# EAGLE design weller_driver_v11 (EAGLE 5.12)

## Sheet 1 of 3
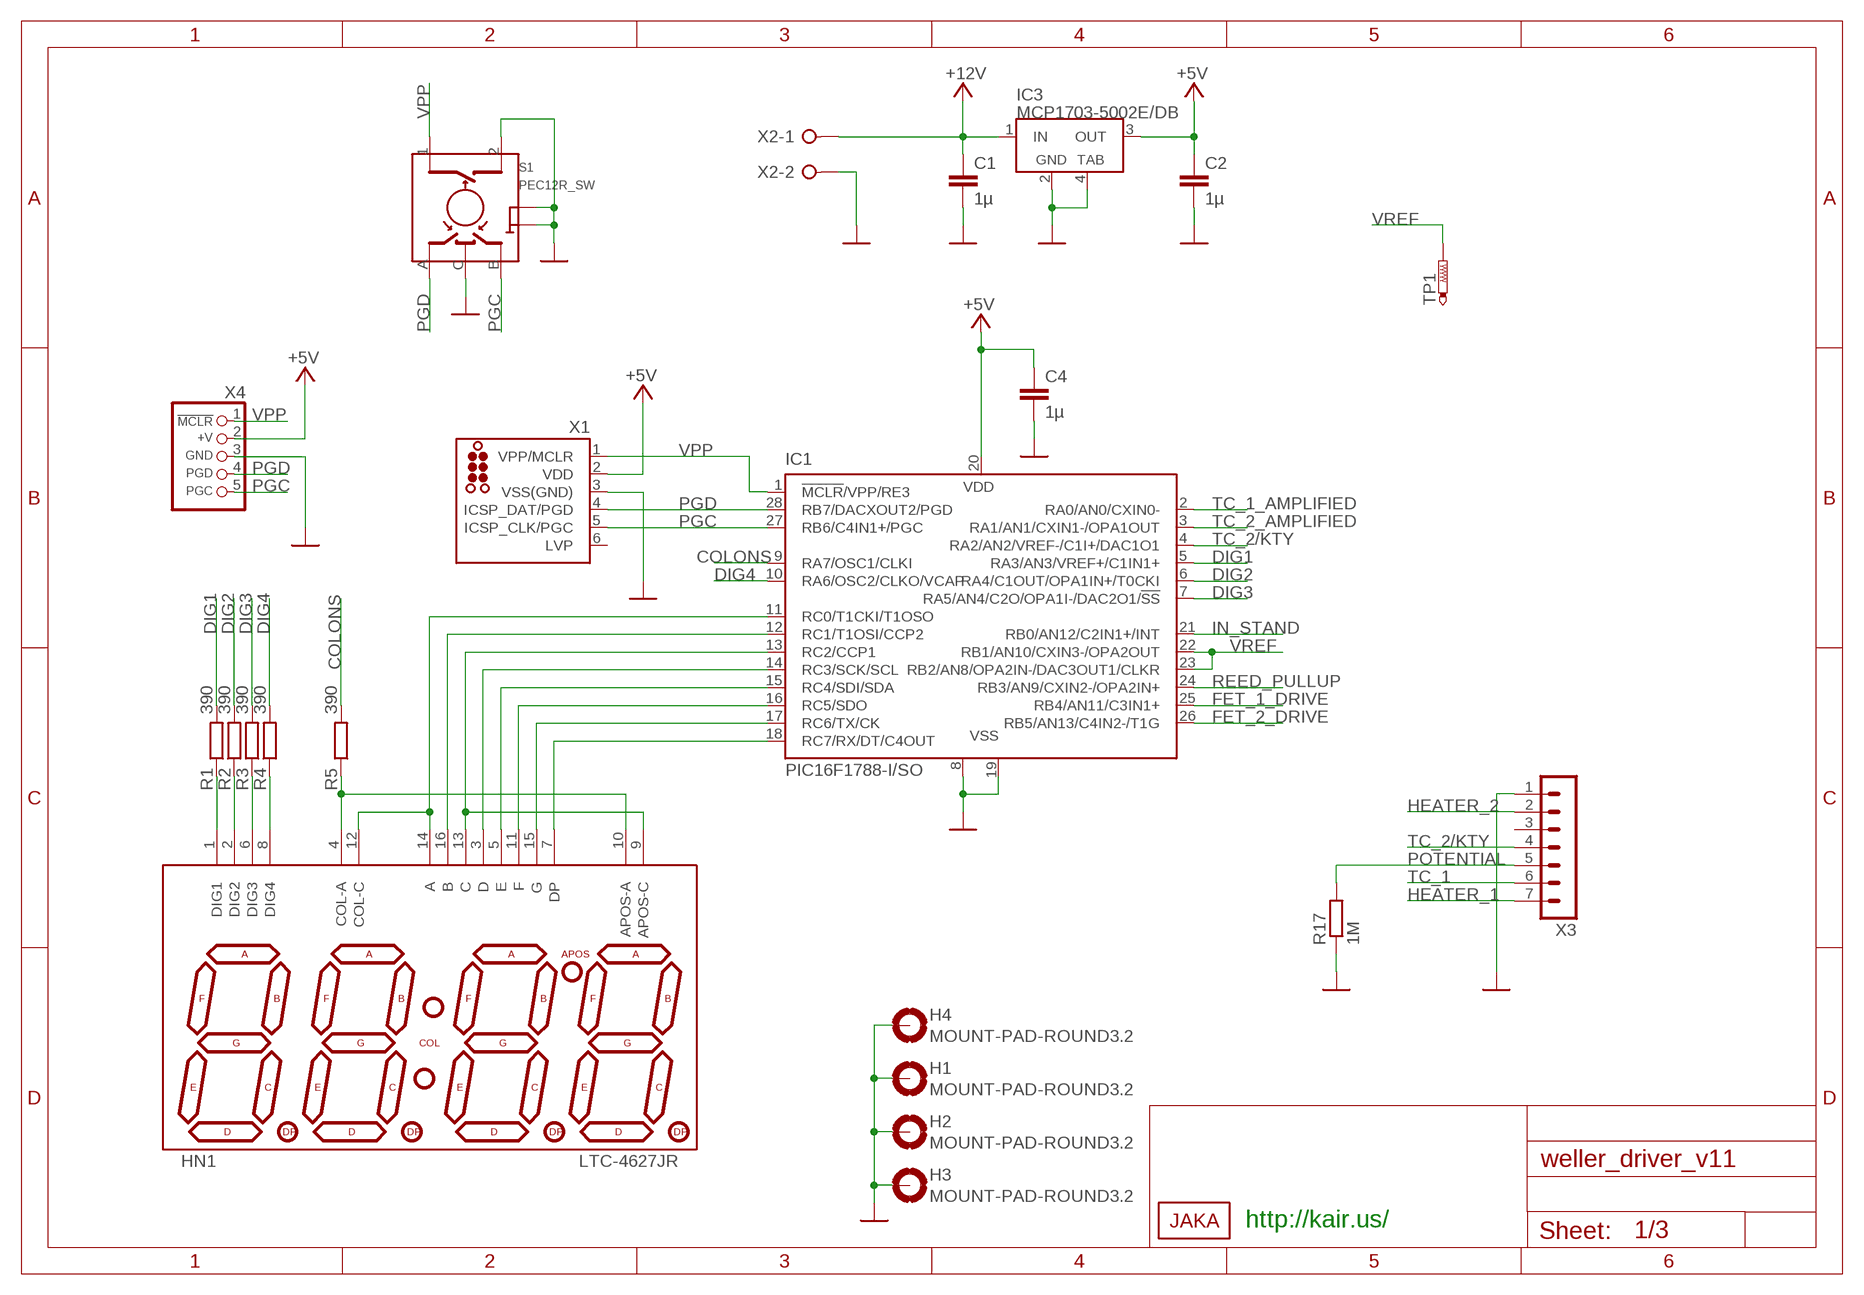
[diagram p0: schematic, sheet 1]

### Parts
C1  1µ  C-EUC0805  [C0805]
C2  1µ  C-EUC0805  [C0805]
C4  1µ  C-EUC0805  [C0805]
H1  MOUNT-PAD-ROUND3.2  [3,2-PAD]
H2  MOUNT-PAD-ROUND3.2  [3,2-PAD]
H3  MOUNT-PAD-ROUND3.2  [3,2-PAD]
H4  MOUNT-PAD-ROUND3.2  [3,2-PAD]
HN1  LTC-4627JR  7-SEGMENT-4DIGIT-YOUNGSUN  [7-SEGMENT-4DIGIT-YOUNGSUN]
IC1  PIC16F1788-I/SO  [SO28W]
IC3  MCP1703-5002E/DB  VREG_3PIN_FIXED_TAB-SOT223  [SOT223]
R1  390  R-EU_R0805  [R0805]
R2  390  R-EU_R0805  [R0805]
R3  390  R-EU_R0805  [R0805]
R4  390  R-EU_R0805  [R0805]
R5  390  R-EU_R0805  [R0805]
R17  1M  R-EU_R0805  [R0805]
S1  PEC12R_SW  [ALPS_EC12E_SW]
TP1  PTR1PAD1-13  [P1-13]
U$1  JAKA_LOGO_SILK_TINY  [JAKA_SILK_TINY]
X1  TC2030-MCP-NL-JKA  [TC2030-MCP-NL-JKA]
X2  W237-02P  [W237-132]
X3  MA07-1  [MA07-1]
X4  CON_HEADER_PRG_PIC_ICSPB  [HEADER_PRG_1X05_ICSP_B]

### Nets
+5V [supply]: C2.1 C4.1 IC1.20(VDD) IC3.3(OUT) X1.2(VDD) X4.2(+V) ; also sheet 2
+12V [iron_power]: C1.1 IC3.1(IN) X2.1 ; also sheet 2
COLONS: IC1.9(RA7/OSC1/CLKI) R5.2
DIG1: IC1.5(RA3/AN3/VREF+/C1IN1+) R1.2
DIG2: IC1.6(RA4/C1OUT/OPA1IN+/T0CKI) R2.2
DIG3: IC1.7(RA5/AN4/C2O/OPA1I-/DAC2O1/!SS) R3.2
DIG4: IC1.10(RA6/OSC2/CLKO/VCAP) R4.2
FET_1_DRIVE: IC1.25(RB4/AN11/C3IN1+) ; also sheet 2
FET_2_DRIVE: IC1.26(RB5/AN13/C4IN2-/T1G) ; also sheet 2
GND [supply]: C1.2 C2.2 C4.2 H1.B3,2(MOUNT) H2.B3,2(MOUNT) H3.B3,2(MOUNT) H4.B3,2(MOUNT) IC1.8(VSS) IC1.19(VSS) IC3.2(GND) IC3.4(GND1) R17.1 S1.2 S1.C S1.GND1(GND) S1.GND2(GND) X1.3(VSS(GND)) X2.2 X3.1 X4.3(GND) ; also sheet 2
HEATER_1 [iron_power]: X3.7 ; also sheet 2
HEATER_2 [iron_power]: X3.2 ; also sheet 2
IN_STAND: IC1.21(RB0/AN12/C2IN1+/INT) ; also sheet 2
N$1: HN1.1(DIG1) R1.1
N$2: HN1.2(DIG2) R2.1
N$3: HN1.6(DIG3) R3.1
N$4: HN1.8(DIG4) R4.1
N$5: HN1.4(COL-A) HN1.10(APOS-A) R5.1
N$6: HN1.12(COL-C) HN1.14(A) IC1.11(RC0/T1CKI/T1OSO)
N$7: HN1.9(APOS-C) HN1.13(C) IC1.13(RC2/CCP1)
N$13: HN1.16(B) IC1.12(RC1/T1OSI/CCP2)
N$17: HN1.3(D) IC1.14(RC3/SCK/SCL)
N$18: HN1.5(E) IC1.15(RC4/SDI/SDA)
N$19: HN1.11(F) IC1.16(RC5/SDO)
N$20: HN1.7(DP) IC1.18(RC7/RX/DT/C4OUT)
N$21: HN1.15(G) IC1.17(RC6/TX/CK)
PGC: IC1.27(RB6/C4IN1+/PGC) S1.B X1.5(ICSP_CLK/PGC) X4.5(PGC)
PGD: IC1.28(RB7/DACXOUT2/PGD) S1.A X1.4(ICSP_DAT/PGD) X4.4(PGD)
POTENTIAL: R17.2 X3.5
REED_PULLUP: IC1.24(RB3/AN9/CXIN2-/OPA2IN+) ; also sheet 2
TC_1: X3.6 ; also sheet 2
TC_1_AMPLIFIED: IC1.2(RA0/AN0/CXIN0-) ; also sheet 2
TC_2/KTY: IC1.4(RA2/AN2/VREF-/C1I+/DAC1O1) X3.4 ; also sheet 2
TC_2_AMPLIFIED: IC1.3(RA1/AN1/CXIN1-/OPA1OUT) ; also sheet 2
VPP: IC1.1(!MCLR!/VPP/RE3) S1.1 X1.1(VPP/MCLR) X4.1(/MCLR)
VREF: IC1.22(RB1/AN10/CXIN3-/OPA2OUT) IC1.23(RB2/AN8/OPA2IN-/DAC3OUT1/CLKR) TP1.TP ; also sheet 2
Unconnected: X1.6(LVP) X3.3

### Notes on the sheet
- http://kair.us/

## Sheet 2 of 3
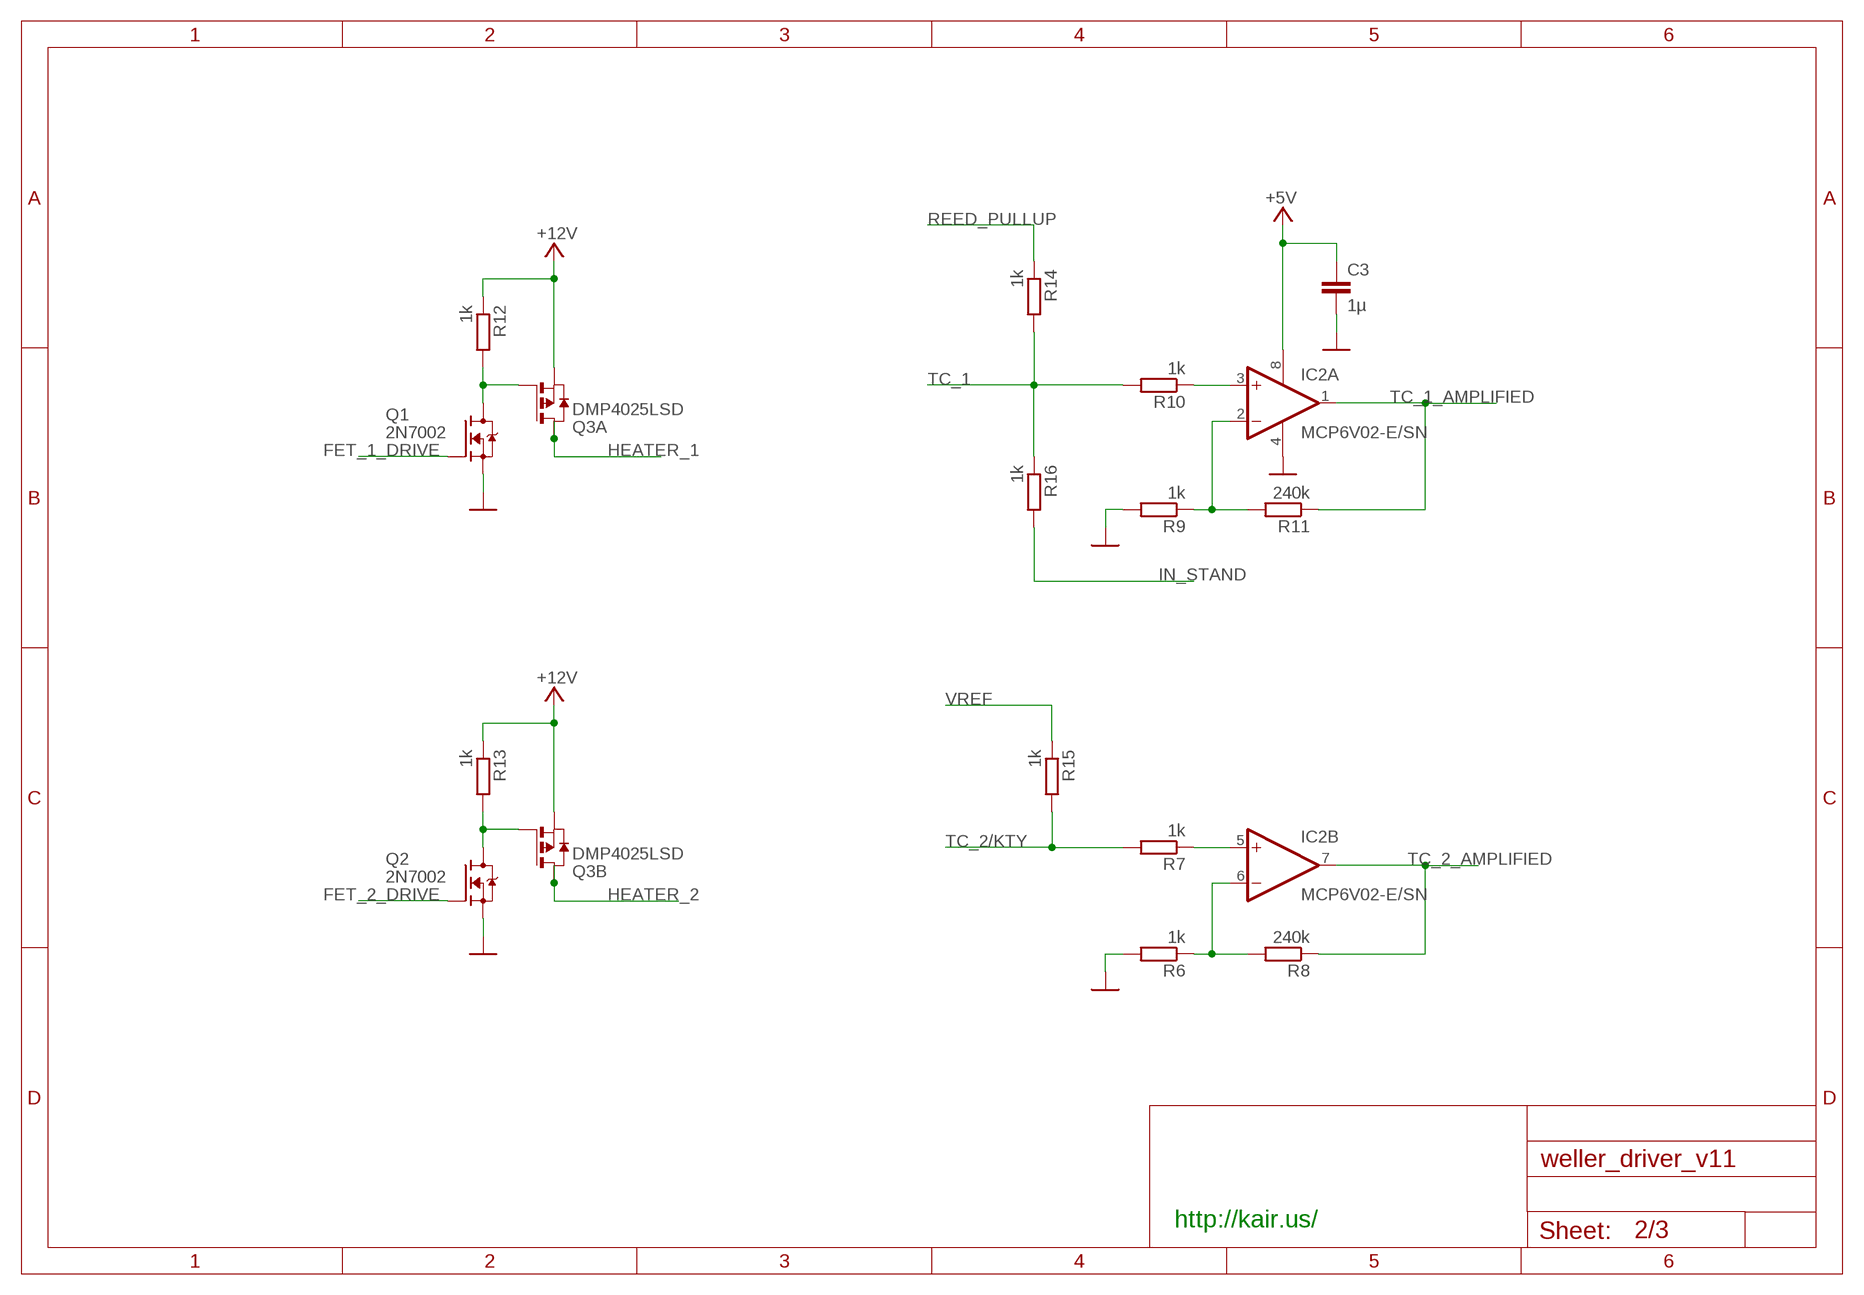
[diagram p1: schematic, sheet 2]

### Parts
C3  1µ  C-EUC0805  [C0805]
IC2  MCP6V02-E/SN  MCP602SN  [SO08]
Q1  2N7002  TRANSISTOR_FET_BS170-SOT-23  [SOT-23]
Q2  2N7002  TRANSISTOR_FET_BS170-SOT-23  [SOT-23]
Q3  DMP4025LSD  PMOS2SO8  [SO08]
R6  1k  R-EU_R0805  [R0805]
R7  1k  R-EU_R0805  [R0805]
R8  240k  R-EU_R0805  [R0805]
R9  1k  R-EU_R0805  [R0805]
R10  1k  R-EU_R0805  [R0805]
R11  240k  R-EU_R0805  [R0805]
R12  1k  R-EU_R0805  [R0805]
R13  1k  R-EU_R0805  [R0805]
R14  1k  R-EU_R0805  [R0805]
R15  1k  R-EU_R0805  [R0805]
R16  1k  R-EU_R0805  [R0805]

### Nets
+5V [supply]: C3.1 IC2.8(P:V+) ; also sheet 1
+12V [iron_power]: Q3.1(A:S) Q3.3(B:S) R12.1 R13.1 ; also sheet 1
FET_1_DRIVE: Q1.1(G) ; also sheet 1
FET_2_DRIVE: Q2.1(G) ; also sheet 1
GND [supply]: C3.2 IC2.4(P:V-) Q1.2(S) Q2.2(S) R6.2 R9.2 ; also sheet 1
HEATER_1 [iron_power]: Q3.7(A:D) Q3.8(A:D2) ; also sheet 1
HEATER_2 [iron_power]: Q3.5(B:D2) Q3.6(B:D) ; also sheet 1
IN_STAND: R16.2 ; also sheet 1
N$22: IC2.3(A:+IN) R10.1
N$23: IC2.2(A:-IN) R9.1 R11.2
N$25: IC2.6(B:-IN) R6.1 R8.2
N$27: IC2.5(B:+IN) R7.1
N$28: Q1.3(D) Q3.2(A:G) R12.2
N$42: Q2.3(D) Q3.4(B:G) R13.2
REED_PULLUP: R14.1 ; also sheet 1
TC_1: R10.2 R14.2 R16.1 ; also sheet 1
TC_1_AMPLIFIED: IC2.1(A:OUT) R11.1 ; also sheet 1
TC_2/KTY: R7.2 R15.2 ; also sheet 1
TC_2_AMPLIFIED: IC2.7(B:OUT) R8.1 ; also sheet 1
VREF: R15.1 ; also sheet 1

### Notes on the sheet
- http://kair.us/

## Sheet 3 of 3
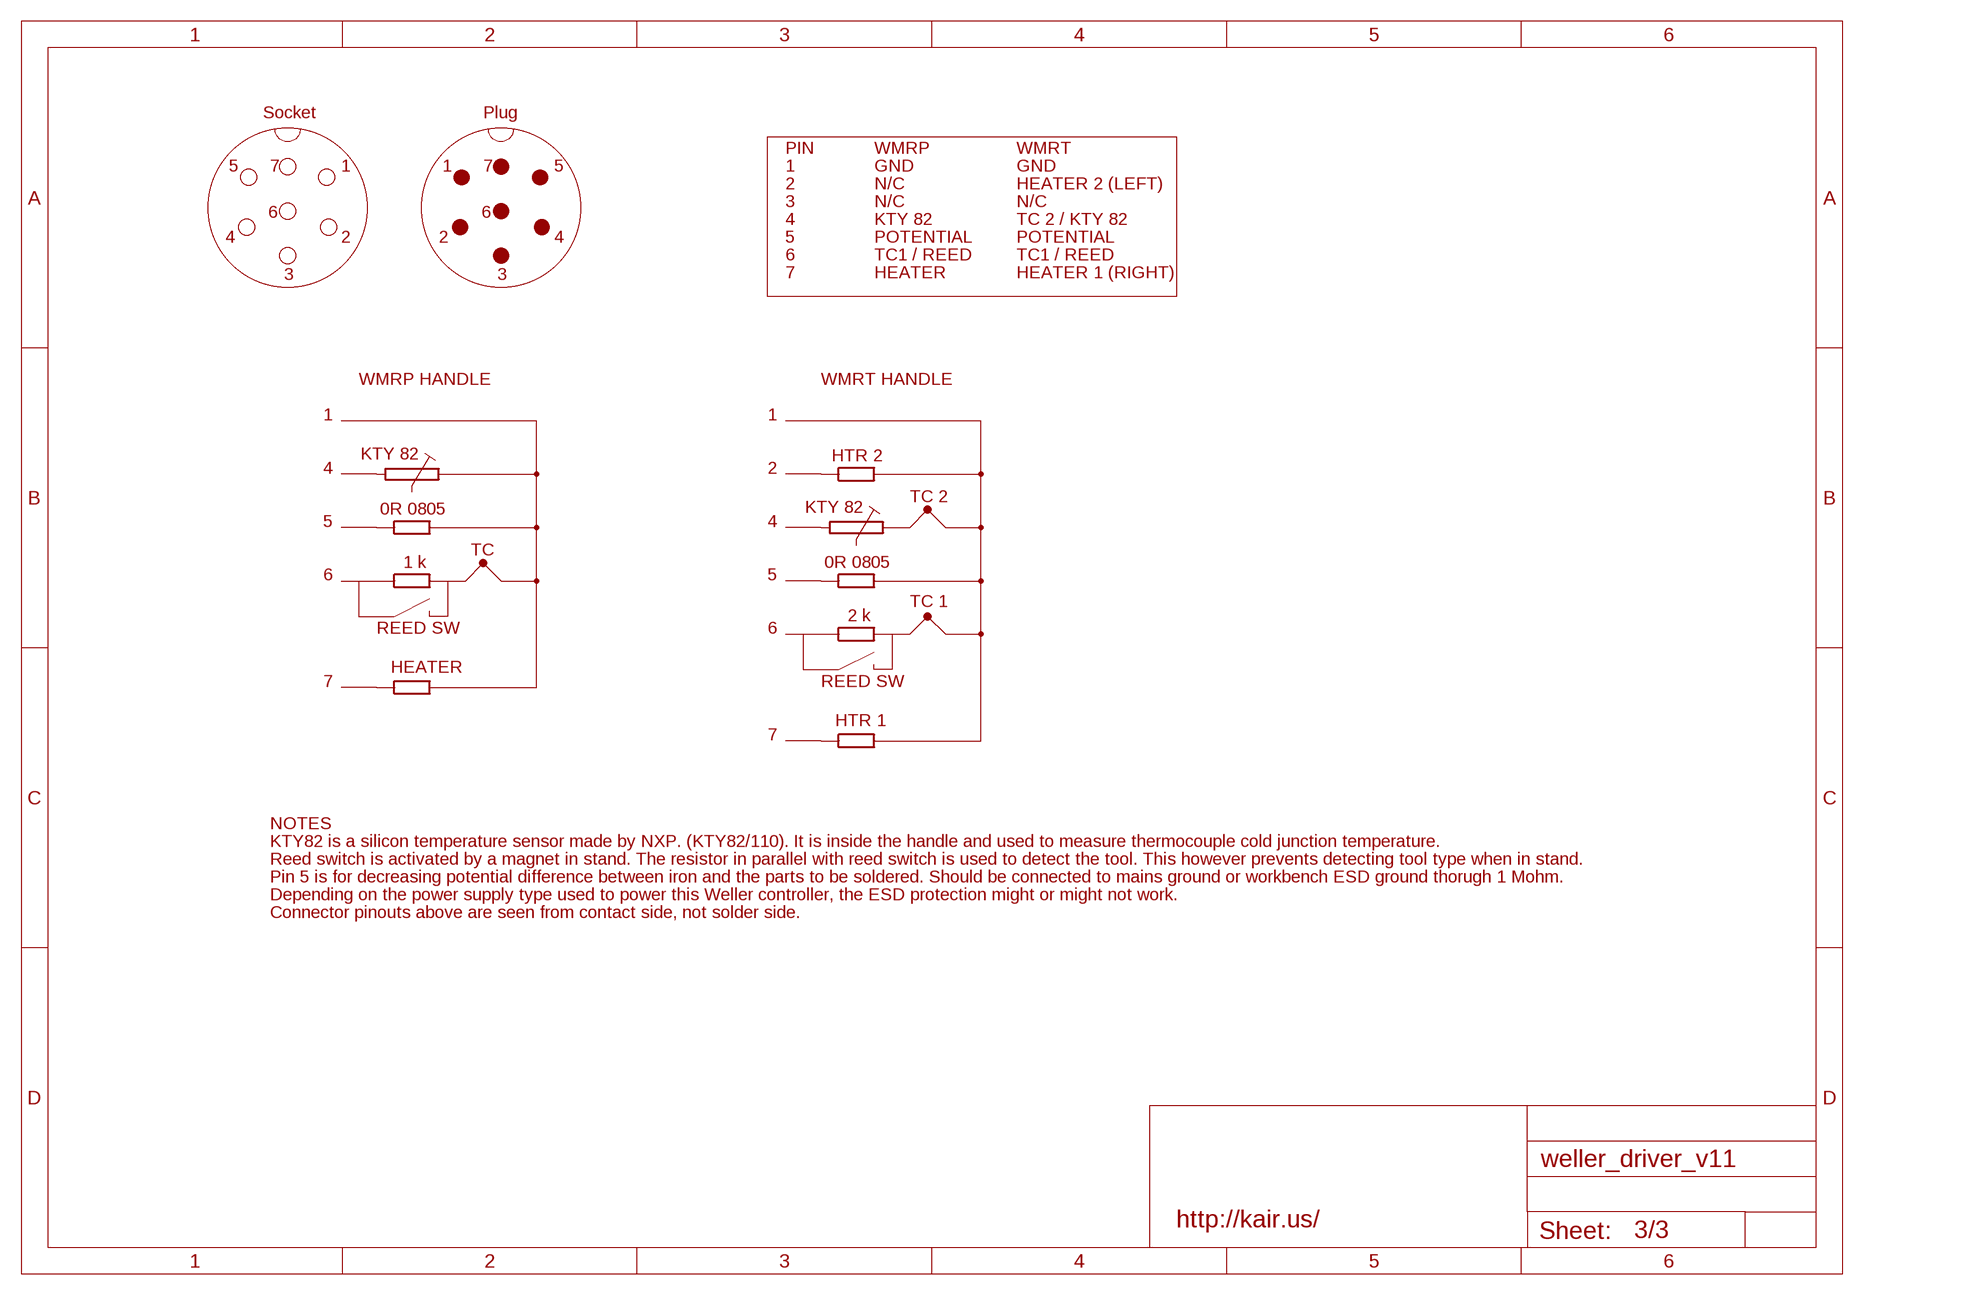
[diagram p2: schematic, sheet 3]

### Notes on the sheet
- Socket | Plug
- PIN | WMRP | WMRT
- 5 | 7 | 1 | 1 | 7 | 5 | 1 | GND | GND
- 2 | N/C | HEATER 2 (LEFT)
- 3 | N/C | N/C
- 6 | 6
- 4 | KTY 82 | TC 2 / KTY 82
- 4 | 2 | 2 | 4 | 5 | POTENTIAL | POTENTIAL
- 6 | TC1 / REED | TC1 / REED
- 3 | 3 | 7 | HEATER | HEATER 1 (RIGHT)
- WMRP HANDLE | WMRT HANDLE
- 1 | 1
- KTY 82 | HTR 2
- 4 | 2
- TC 2
- 0R 0805 | KTY 82
- 5 | 4
- TC
- 1 k | 0R 0805
- 6 | 5
- TC 1
- 2 k
- REED SW | 6
- HEATER
- 7 | REED SW
- HTR 1
- 7
- NOTES
- KTY82 is a silicon temperature sensor made by NXP. (KTY82/110). It is inside the handle and used to measure thermocouple cold junction temperature.
- Reed switch is activated by a magnet in stand. The resistor in parallel with reed switch is used to detect the tool. This however prevents detecting tool type when in stand.
- Pin 5 is for decreasing potential difference between iron and the parts to be soldered. Should be connected to mains ground or workbench ESD ground thorugh 1 Mohm.
- Depending on the power supply type used to power this Weller controller, the ESD protection might or might not work.
- Connector pinouts above are seen from contact side, not solder side.
- http://kair.us/

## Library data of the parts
C1-C4 = dual_atari:C-EU: CAPACITOR, European symbol
H1-H4 = dual_atari:MOUNT-PAD-ROUND: MOUNTING PAD, round
HN1 = omat:7-SEGMENT-4DIGIT-YOUNGSUN: This is a part for the 4-Digit 7-segment LEDs from Young Sun. Different from the Digikey LEDs, all 16 pins are used. The LONGPADS Variant is used for a test jig, but you may like it because there is more pad to solder to. If you are concerned about routing space, the standard works just fine though.
IC1 = omat:PIC16F1788
IC2 = omat:MCP602: Single Op Amp 2.7V to 6.0V Single Supply CMOS Source: http://ww1.microchip.com/downloads/en/DeviceDoc/21314g.pdf
IC3 = omat:VREG_3PIN_FIXED_TAB
Q1 Q2 = omat:TRANSISTOR_FET_BS170: N-Channel Enhancement Mode Field Effect Transistor
Q3 = omat:PMOS2: DUAL 30V P-CHANNEL ENHANCEMENT MODE MOSFET Source: Data sheet SOP8 Source: Data sheet MSOP8
R1-R17 = dual_atari:R-EU_: RESISTOR, European symbol
S1 = omat:PEC12R_SW
TP1 = testpad:PTR1: TEST PIN
U$1 = dual_atari:JAKA_LOGO
X1 = dual_atari:TC2030: TAG-CONNECT ISP Connector Manufacturer: Tag-Connect Cable for easy In-Circuit PCB Programming. Designed for Microchip ICD2, suitable for many others. Two variants - one "with legs" (for hads-free fit on PCB) and another "without legs" for quick programming. PADDescription 1MCLR/Vpp 2Vdd 3GND 4PGD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
X2 = omat:W237-02P: WAGO SREW CLAMP; OC_FARNELL: unknown; OC_NEWARK: unknown
X3 = omat:MA07-1: PIN HEADER; OC_FARNELL: unknown; OC_NEWARK: unknown
X4 = omat:CON_HEADER_PRG_PIC_ICSP: 5-pin PIC In Circuit Serial Programming header

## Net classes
1 supply: width 0.4 mm, drill 0.7 mm, clearance 0.25 mm
2 iron_power: width 1 mm, drill 0.7 mm, clearance 0.25 mm

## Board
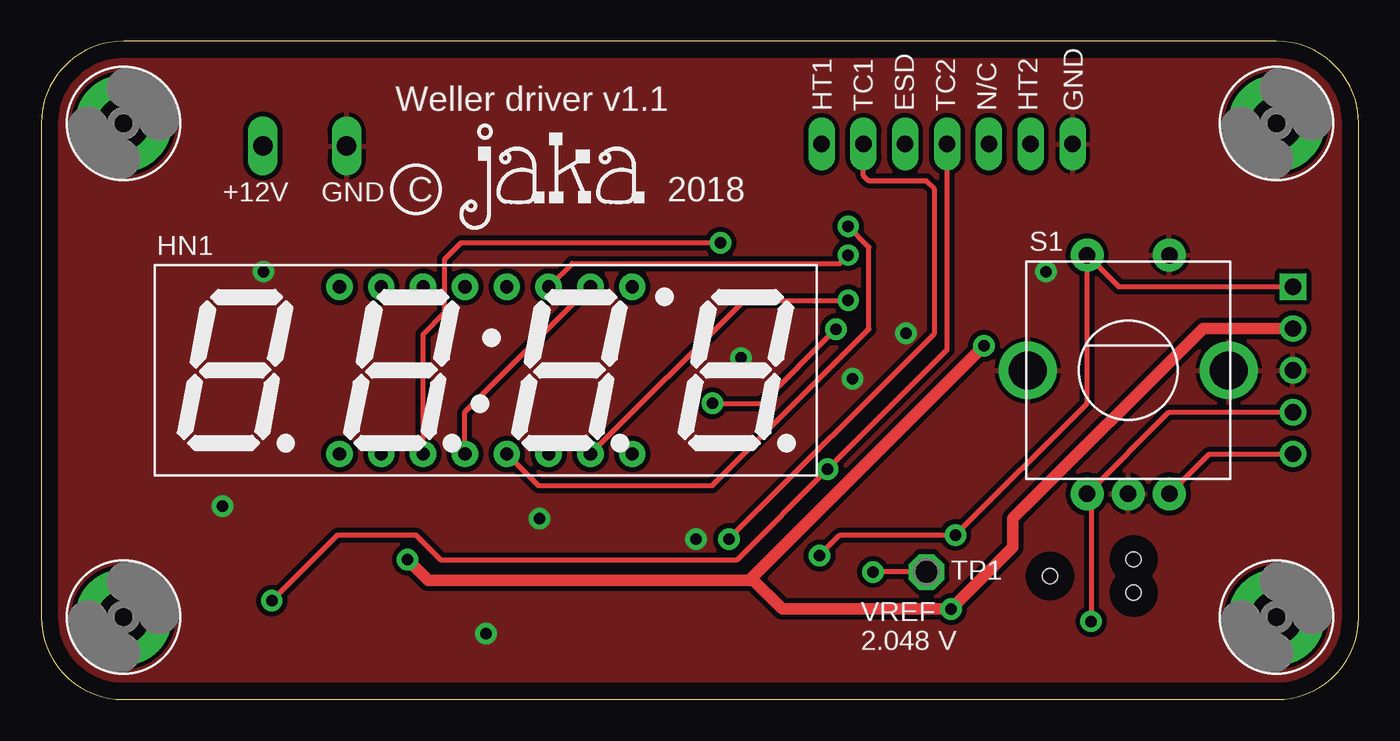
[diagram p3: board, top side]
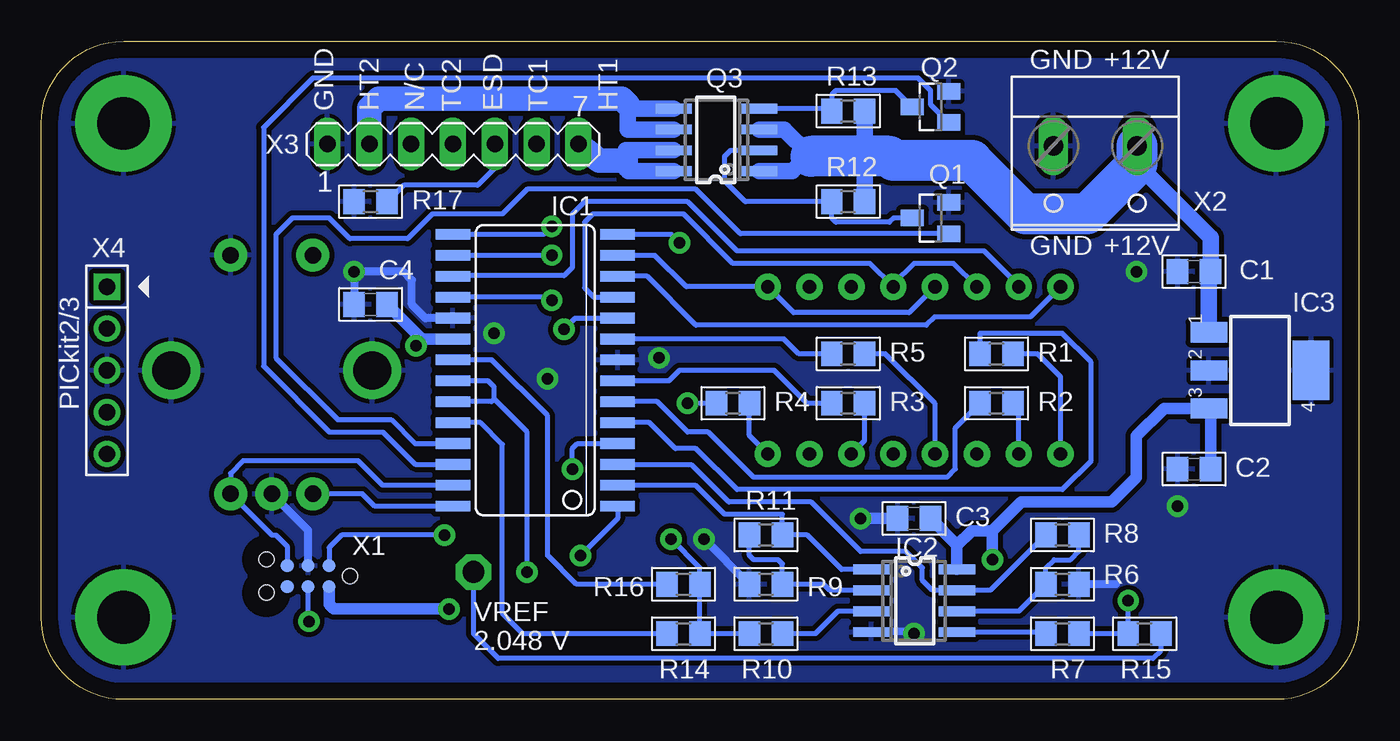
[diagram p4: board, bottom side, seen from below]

Size 80 x 40 mm. Coordinates in mm from the lower left corner, seen from the top.
Outline: 75,0 arc90 80,5 80,35 arc90 75,40 5,40 arc90 0,35 0,5 arc90 5,0 75,0
Copper layers (1*16): Top 0.035mm / dielectric 1.5mm / Bottom 0.035mm
Design rules "default *": minimum track width 0.25mm, minimum drill 0.7mm, track to track 0.25mm, track to pad 0.25mm, pad to pad 0.25mm, via to via 0.25mm, smd to smd 0.25mm, copper to edge 40mil, drill to drill 8mil, minimum pad ring 0.3mm, minimum via ring 0.3mm, stop-mask expansion 4mil, vias tented up to drill 0mil, thermal gap 10mil

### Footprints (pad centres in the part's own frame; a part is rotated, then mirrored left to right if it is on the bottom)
C0805 = smd 1.3 x 1.5: 1 -1,0; 2 1,0
3,2-PAD = drill 3.2 pad 5.842 round: B3,2 0,0
7-SEGMENT-4DIGIT-YOUNGSUN = drill 0.8 pad 1.6 round: 1 -8.89,-5.08; 2 -6.35,-5.08; 3 -3.81,-5.08; 4 -1.27,-5.08; 5 1.27,-5.08; 6 3.81,-5.08; 7 6.35,-5.08; 8 8.89,-5.08; 9 8.89,5.08; 10 6.35,5.08; 11 3.81,5.08; 12 1.27,5.08; 13 -1.27,5.08; 14 -3.81,5.08; 15 -6.35,5.08; 16 -8.89,5.08
SO28W = smd 0.65 x 2.1: 1 -8.255,-5; 2 -6.985,-5; 3 -5.715,-5; 4 -4.445,-5; 5 -3.175,-5; 6 -1.905,-5; 7 -0.635,-5; 8 0.635,-5; 9 1.905,-5; 10 3.175,-5; 11 4.445,-5; 12 5.715,-5; 13 6.985,-5; 14 8.255,-5; 15 8.255,5; 16 6.985,5; 17 5.715,5; 18 4.445,5; 19 3.175,5; 20 1.905,5; 21 0.635,5; 22 -0.635,5; 23 -1.905,5; 24 -3.175,5; 25 -4.445,5; 26 -5.715,5; 27 -6.985,5; 28 -8.255,5
SO08 = smd 0.6 x 2.2: 1 -1.905,-2.6; 2 -0.635,-2.6; 3 0.635,-2.6; 4 1.905,-2.6; 5 1.905,2.6; 6 0.635,2.6; 7 -0.635,2.6; 8 -1.905,2.6
SOT223 = smd 1.219 x 2.235: 1 -2.311,-3.099; 2 0,-3.099; 3 2.311,-3.099 | smd 3.6 x 2.2: 4 0,3.099
SOT-23 = smd 1 x 1.4: 1 -0.95,-1.1; 2 0.95,-1.1; 3 0,1.1
R0805 = smd 1.3 x 1.5: 1 -1,0; 2 1,0
ALPS_EC12E_SW = drill 1 pad 2 round: 1 -2.5,7; 2 2.5,7; A -2.5,-7.5; B 2.5,-7.5; C 0,-7.5 | drill 2.3 pad 3.5 round: GND1 -6.1,0; GND2 6.1,0
P1-13 = drill 1.321 pad 2.159 octagon: TP 0,0
TC2030-MCP-NL-JKA = smd 0.787 x 0.787: 1 1.27,-0.635; 2 1.27,0.635; 3 2.54,-0.635; 4 2.54,0.635; 5 3.81,-0.635; 6 3.81,0.635 | hole 0.9: 0,0; 5.08,-1.016; 5.08,1.016
W237-132 = drill 1.194 long: 1 -2.54,-0.635; 2 2.54,-0.635
MA07-1 = drill 1 long: 1 -7.62,0; 2 -5.08,0; 3 -2.54,0; 4 0,0; 5 2.54,0; 6 5.08,0; 7 7.62,0
HEADER_PRG_1X05_ICSP_B = drill 1 square: 1 -5.08,0 | drill 1 round: 2 -2.54,0; 3 0,0; 4 2.54,0; 5 5.08,0

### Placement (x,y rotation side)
C1  10,26 180 bottom
C2  10,14 180 bottom
C3  27,11 180 bottom
C4  60,24 180 bottom
H1  5,5 0 top
H2  75,5 0 top
H3  5,35 0 top
H4  75,35 0 top
HN1  27,20 0 top
IC1  50,20 90 bottom
IC2  27,6 270 bottom
IC3  6,20 270 bottom
Q1  26,29.25 90 bottom
Q2  26,36 90 bottom
Q3  39,34 90 bottom
R1  22,21 180 bottom
R2  22,18 180 bottom
R3  31,18 180 bottom
R4  38,18 180 bottom
R5  31,21 180 bottom
R6  18,7 0 bottom
R7  18,4 0 bottom
R8  18,10 0 bottom
R9  36,7 180 bottom
R10  36,4 180 bottom
R11  36,10 180 bottom
R12  31,30.25 180 bottom
R13  31,35.75 180 bottom
R14  41,4 0 bottom
R15  13,4 180 bottom
R16  41,7 180 bottom
R17  60,30.25 0 bottom
S1  66,20 0 top
TP1  53.75,7.75 0 top
U$1  31,31.75 0 top
X1  61.25,7.5 180 bottom
X2  16,33 180 bottom
X3  55,33.75 0 bottom
X4  76,20 270 bottom

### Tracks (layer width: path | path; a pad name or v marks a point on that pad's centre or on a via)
+5V  (via drill 0.7)
  Top 0.7: 43.12,7.38 43,7.25 23.5,7.25 v22.25,8.5 | 43.12,7.38 v57.25,21.5 | 43.12,7.38 45,5.5 v55.25,5.5 59,9.25 59,11 70.54,22.54 X4.2
  Bottom 0.5: 9,17.59 IC3.3
  Bottom 0.7: C2.1 9,17.59 | C3.1 24.4,9.4 IC2.8 24.4,9.35 23.5,10.25 22.25,10.25 | IC3.3 11.81,17.69 13.5,16 13.5,13.5 15,12 20.5,12 22.25,10.25 | 56.91,21.91 IC1.20 | 56.91,21.91 C4.1 | 56.91,21.91 56.91,21.84 v57.25,21.5 | X1.2 62.52,5.77 62.25,5.5 v55.25,5.5 | 22.25,10.25 v22.25,8.5
+12V
  Bottom 1: 13.46,32.54 9,28.08 C1.1 9.1,25.9 IC3.1 | R13.1 30,33 R12.1 | Q3.3 34.88,34.63 33.38,33.12 | 33.25,33 33.38,33.12 | Q3.1 34.41,32.09 33.38,33.12
  Bottom 2: 28.25,32.75 28.5,33
  Bottom 2.5: X2.1 13.46,32.54 16.5,29.5 20.25,29.5 23.5,32.75 28.25,32.75 | 28.5,33 30,33 33.25,33
COLONS
  Bottom 0.3: R5.2 34,21 34.91,21.91 IC1.9
DIG1
  Bottom 0.3: IC1.5 43.08,16.82 41.5,15.25 40.25,15.25 37.75,12.75 18,12.75 16.25,14.5 16.25,20.5 18,22.25 23,22.25 R1.2
DIG2
  Bottom 0.3: R2.2 24.5,16.5 24.5,14 25,13.5 36.75,13.5 39.5,16.25 40.75,16.25 42.59,18.09 IC1.6
DIG3
  Bottom 0.3: R3.2 33.5,18 35.5,20 41.25,20 41.88,19.36 IC1.7
DIG4  (via drill 0.7)
  Top 0.3: v40.75,18 43.75,18 v48.25,22.5
  Bottom 0.3: R4.2 v40.75,18 | v48.25,22.5 47.58,23.18 IC1.10
FET_1_DRIVE
  Bottom 0.3: IC1.25 57.3,15.55 58.75,17 62,17 65.75,20.75 65.75,28.25 64.75,29.25 62.5,29.25 61.25,28 57.75,28 56.25,29.5 52,29.5 50.5,31 40.25,31 37.55,28.3 Q1.1
FET_2_DRIVE
  Bottom 0.3: IC1.26 57.28,14.29 59.25,16.25 62.5,16.25 66.5,20.25 66.5,34.75 63.5,37.75 26.75,37.75 26,37 26,36.15 Q2.1
GND  (via drill 0.7)
  Bottom 0.5: IC2.4 27.1,4.15 v27,4 | R9.2 v39.75,9.75 | 14.75,7 R6.2 | IC1.19 56.67,23.18 57.5,24 57.5,25.5 58,26 60.5,26 61,25.5 C4.2 | S1.C 63.79,10.29 X1.3
  Bottom 0.7: C3.2 v30.25,11
  other vias: 13.5,26 11,11.75 42.5,20.75 52.5,22.25 49.25,19.5 61,26
  pour Top (isolate 0.3): 5,0 75,0 arc90 80,5 80,35 arc90 75,40 5,40 arc90 0,35 0,5 arc90
  pour Bottom (isolate 0.3): 5,0 75,0 arc90 80,5 80,35 arc90 75,40 5,40 arc90 0,35 0,5 arc90
HEATER_1
  Bottom 1: Q3.7 44.5,33.37 44.5,32.75 44.5,32.25 44.34,32.09 Q3.8
  Bottom 1.5: X3.7 46.13,32.75 44.5,32.75
HEATER_2
  Bottom 1: Q3.6 44.38,34.63 44.38,35.75 | 44.38,35.75 44.38,36.13 | Q3.5 44.23,35.91 44.38,35.75
  Bottom 1.5: X3.2 60.08,35.92 59.5,36.5 44.75,36.5 44.38,36.13
IN_STAND
  Bottom 0.3: R16.2 47.5,7 49.25,8.75 49.25,17.25 52.63,20.64 IC1.21
N$1
  Bottom 0.3: R1.1 19.5,21 18.11,19.61 HN1.1
N$2
  Bottom 0.3: HN1.2 20.65,17.65
  Bottom 0.5: 20.65,17.65 R2.1
N$3
  Bottom 0.3: HN1.6 30,15.73 R3.1
N$4
  Bottom 0.3: HN1.8 37,16.03 R4.1
N$5
  Top 0.3: HN1.10 25.73,17.46 HN1.4
  Bottom 0.3: R5.1 28.75,21 25.73,17.98 HN1.4
N$6
  Bottom 0.3: IC1.11 46.45,24.45 47,25 47,29 46.5,29.5 41,29.5 38,26.5 29.69,26.5 HN1.12 | 28.27,25.23 27,26.5 24.61,26.5 HN1.14
  Bottom 0.5: 28.27,25.23 HN1.12
N$7
  Bottom 0.3: HN1.13 27.31,23.5 34.31,23.5 HN1.9 40.83,25.08 42.73,26.98 IC1.13
N$13
  Bottom 0.3: IC1.12 43.22,25.71 40.25,22.75 26.25,22.75 25.75,23.25 19.94,23.25 HN1.16
N$17  (via drill 0.7)
  Top 0.3: v41.25,27.75 25.5,27.75 24.5,26.75 24.5,23.5 23.19,22.19 HN1.3
  Bottom 0.3: IC1.14 41.74,28.25 v41.25,27.75
N$18  (via drill 0.7)
  Top 0.3: HN1.5 30.19,13 40.75,13 50.25,22.5 50.25,27.5 v49,28.75
  Bottom 0.3: IC1.15 49.49,28.25 v49,28.75
N$19  (via drill 0.7)
  Top 0.3: v49,27 48.5,26.5 32.23,26.5 HN1.11
  Bottom 0.3: IC1.16 49.52,26.98 v49,27
N$20  (via drill 0.7)
  Top 0.3: v49,24.25 42.68,24.25 HN1.7
  Bottom 0.3: IC1.18 49.2,24.45 v49,24.25
N$21
  Bottom 0.3: 20.65,25.15 22.75,27.25 37.75,27.25 40.75,30.25 47,30.25 47.75,29.5 47.75,26.25 48.25,25.75 54.97,25.75
  Bottom 0.5: HN1.15 20.65,25.15 | 54.97,25.75 IC1.17
N$22
  Bottom 0.3: IC2.3 31.64,5.37 33,4 R10.1
N$23
  Bottom 0.3: IC2.2 32.13,6.63 32.5,7 R9.1 35,8.25 35.25,8.5 36.75,8.5 37,8.75 R11.2
N$25
  Bottom 0.3: IC2.6 20.64,5.37 R6.1 19,8 18.5,8.5 17.5,8.5 17,9 R8.2
N$27
  Bottom 0.3: 19.09,4.09 IC2.5
  Bottom 0.5: R7.1 19.09,4.09
N$28
  Bottom 0.3: Q3.2 38.13,33.37 38.5,33 38.5,31.5 37.25,30.25 R12.2 32,29.25 31.75,29 28.5,29 28.25,29.25 Q1.3
N$42
  Bottom 0.3: Q3.4 32.09,35.91 R13.2 32,36.75 31.75,37 28.1,37 Q2.3
PGC
  Top 0.3: X4.5 70.92,14.92 S1.B
  Bottom 0.3: X1.5 65.06,9.31 65.75,10 66,10 S1.B 68.5,13.75 67.75,14.5 60.75,14.5 59.27,13.02 IC1.27
PGD  (via drill 0.7)
  Top 0.3: v63.75,4.75 63.75,12.25 S1.A 68.46,17.46 X4.4
  Bottom 0.3: IC1.28 59.74,11.74 60.5,12.5 S1.A | X1.4 63.79,4.79 v63.75,4.75
POTENTIAL
  Bottom 0.3: X3.5 52.46,32.29 53.5,31.25 58,31.25 R17.2
REED_PULLUP
  Bottom 0.3: R14.1 50.75,4 52,5.25 52,15.5 53.33,16.82 IC1.24
TC_1  (via drill 0.7)
  Top 0.3: X3.6 49.92,31.83 50.25,31.5 53.75,31.5 54.25,31 54.25,22.25 v41.75,9.75
  Bottom 0.3: R10.2 R14.2 R16.1 40,8 v41.75,9.75
TC_1_AMPLIFIED
  Bottom 0.3: IC2.1 31.41,7.91 33.5,10 R11.1 35,11.25 38.5,11.25 40.25,13 44.98,13
  Bottom 0.5: 44.98,13 IC1.2
TC_2/KTY  (via drill 0.7)
  Top 0.3: X3.4 55,21.25 v47.75,14 42.25,8.5 24.25,8.5 22.75,10 18,10 v14,6
  Bottom 0.3: R7.2 R15.2 v14,6 | IC1.4 47.45,15.55 47.75,15.25 v47.75,14
TC_2_AMPLIFIED
  Bottom 0.3: R8.1 22.36,6.63 IC2.7 25.89,6.63 26.5,7.25 26.5,8 27.5,9 30.25,9 33.25,12 38.25,12 40.5,14.25 44.97,14.25
  Bottom 0.5: 44.97,14.25 IC1.3
VPP  (via drill 0.7)
  Top 0.3: v47.25,8.75 48.5,10 v55.5,10 63.5,18 S1.1 65.42,25.08 X4.1
  Bottom 0.3: IC1.1 45,11 v47.25,8.75 | X1.1 62.52,9.23 61.75,10 v55.5,10
VREF  (via drill 0.7)
  Top 0.3: TP1.TP v50.5,7.75
  Bottom 0.3: IC1.22 52.87,19.36 52.5,19 52.5,18.25 | 52.5,18.25 52.66,18.09 IC1.23 | v50.5,7.75 50.5,16.25 52.5,18.25 | R15.1 12,3 12.5,2.5 52.25,2.5 53.75,4 TP1.TP
  Bottom 0.5: IC1.23 55.09,18

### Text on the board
tPlace: Weller driver v1.1 | HT1 | TC1 | ESD | TC2 | N/C | HT2 | GND | +12V | GND | C | 2018 | VREF | 2.048 V
bPlace: +12V | GND | HT1 | TC1 | ESD | TC2 | N/C | HT2 | GND | +12V | GND | PICkit2/3 | VREF | 2.048 V
tStop: WWW.KAIR.US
